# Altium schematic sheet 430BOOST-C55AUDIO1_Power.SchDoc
size A4; PageSetup: Record=PageOptions|CenterHorizontal=True|CenterVertical=True|PrintScale=1.00|XCorrection=1.00|YCorrection=1.00|PrintKind=0|BorderSize=5000000|LeftOffset=0|BottomOffset=0|Orientation=2|PaperLength=1000|PaperWidth=1000|Scale=100|PaperSource=7|PrintQuality=-4|MediaType=1|DitherType=10|PaperKind=A4|PrintScaleMode=1
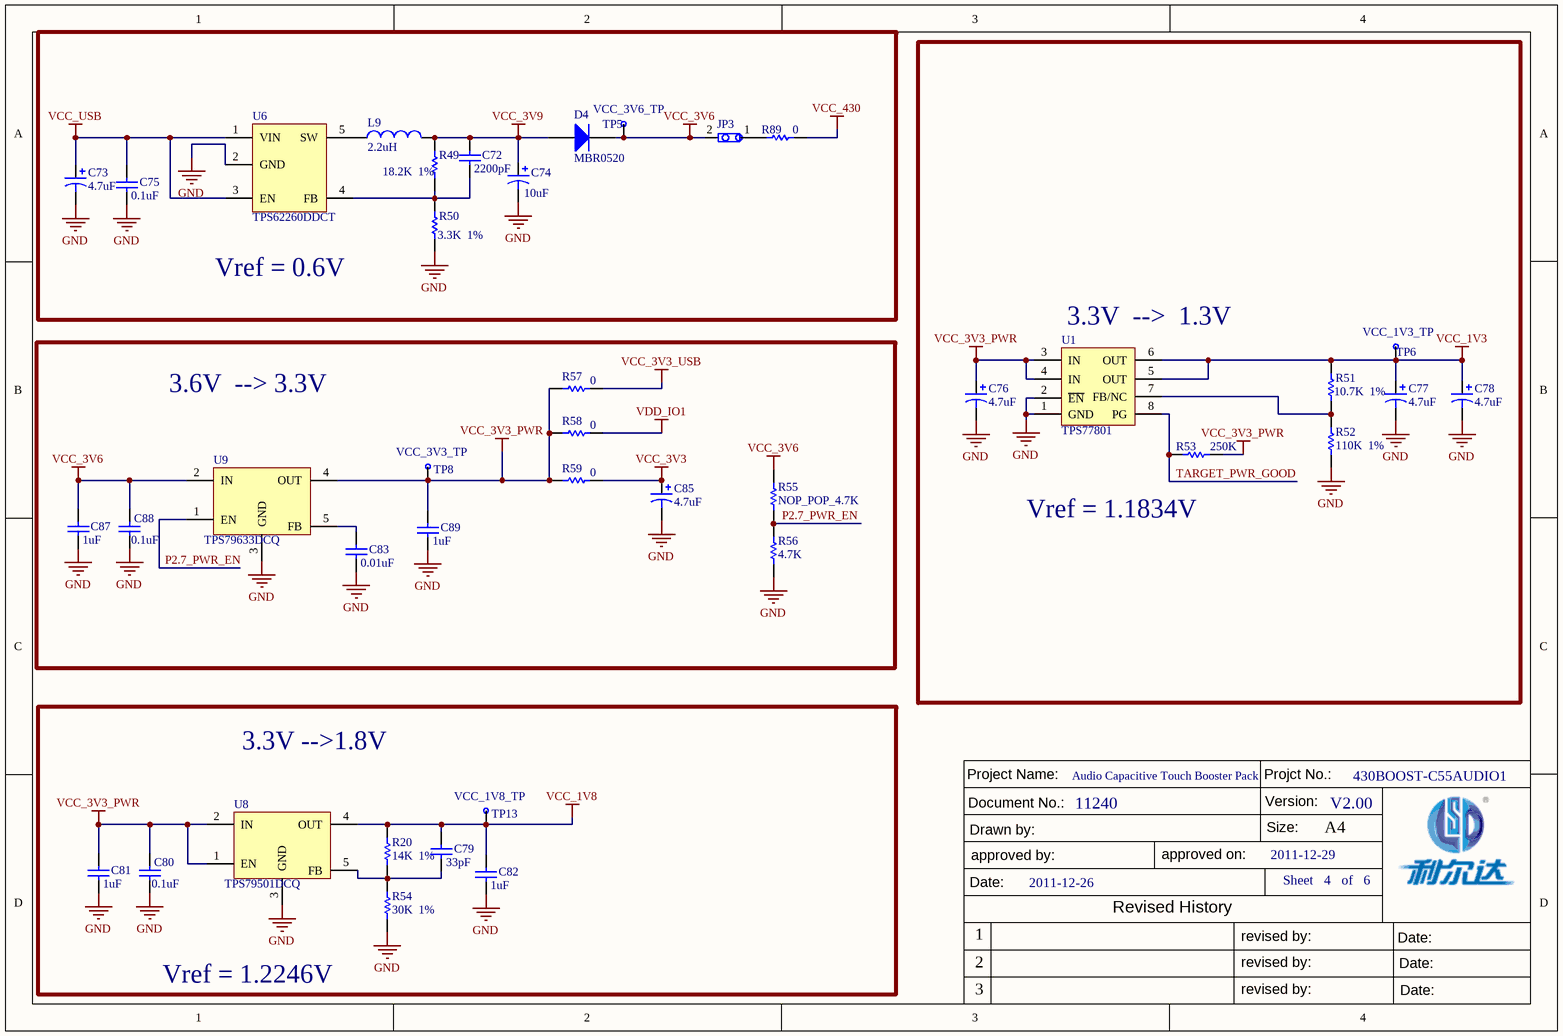
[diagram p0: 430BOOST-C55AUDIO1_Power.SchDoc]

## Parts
C72  2200pF  [0402-C]
C73  4.7uF  [0805-c]
C74  10uF  [0805-c]
C75  0.1uF  [0402-C]
C76  4.7uF  [0805-c]
C77  4.7uF  [0805-c]
C78  4.7uF  [0805-c]
C79  33pF  [0402-C]
C80  0.1uF  [0402-C]
C81  1uF  [0603-C]
C82  1uF  [0603-C]
C83  0.01uF  [0402-C]
C85  4.7uF  [0805-c]
C87  1uF  [0603-C]
C88  0.1uF  [0402-C]
C89  1uF  [0603-C]
D4  MBR0520  [SOD-123-1]
JP3  JUMPER  [SIP2-2.54]  (value not drawn)
L9  2.2uH  [VLF3010A]
R20  14K  1%  [0402-R]
R49  18.2K  1%  [0402-R]
R50  3.3K  1%  [0402-R]
R51  10.7K  1%  [0402-R]
R52  110K  1%  [0402-R]
R53  250K  [0402-R]
R54  30K  1%  [0402-R]
R55  NOP_POP_4.7K  [0402-R]
R56  4.7K  [0402-R]
R57  0  [0402-R]
R58  0  [0402-R]
R59  0  [0402-R]
R89  0  [0402-R]
TP5  VCC_3V6_TP  [SIP1-TEST]
TP6  VCC_1V3_TP  [SIP1-TEST]
TP8  VCC_3V3_TP  [SIP1-TEST]
TP13  VCC_1V8_TP  [SIP1-TEST]
U1  TPS77801  [SOIC-8P]
U6  TPS62260DDCT  [SOT-23-5P]
U8  TPS79501DCQ  [SOT-223-6]
U9  TPS79633DCQ  [SOT-223-6]

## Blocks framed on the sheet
Vref = 0.6V: C72-C75 D4 JP3 L9 R49 R50 R89 TP5 U6
3.6V  --> 3.3V: C83 C85 C87-C89 R55-R59 TP8 U9

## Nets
GND: C73.2 C74.2 C75.1 C76.2 C77.2 C78.2 C80.1 C81.1 C82.1 C83.1 C85.2 C87.1 C88.1 C89.1 R50.1 R52.1 R54.2 R56.1 U1.1(GND) U1.2(~{EN}) U6.2(GND) U8.3(GND) U9.3(GND)
VCC_1V3: C77.1 C78.1 R51.2 TP6.1 U1.5(OUT) U1.6(OUT)
VCC_1V8: C79.2 C82.2 R20.2 TP13.1 U8.4(OUT)
VCC_3V3: C85.1 R59.2
VCC_3V3_PWR: C76.1 C80.2 C81.2 C89.2 R53.2 R57.1 R58.1 R59.1 TP8.1 U1.3(IN) U1.4(IN) U8.1(EN) U8.2(IN) U9.4(OUT)
VCC_3V3_USB: R57.2
VCC_3V6: C87.2 C88.2 D4.2(K) JP3.2 R55.2 TP5.1 U9.2(IN)
VCC_3V9: C72.2 C74.1 D4.1(A) L9.2 R49.2
VCC_430: R89.2
VCC_USB: C73.1 C75.2 U6.1(VIN) U6.3(EN)
VDD_IO1: R58.2
P2.7_PWR_EN: R55.1 R56.2 U9.1(EN)
TARGET_PWR_GOOD: R53.1 U1.8(PG)
NetC72_1: C72.1 R49.1 R50.2 U6.4(FB)
NetC79_1: C79.1 R20.1 R54.1 U8.5(FB)
NetC83_2: C83.2 U9.5(FB)
NetJP3_1: JP3.1 R89.1
NetL9_1: L9.1 U6.5(SW)
NetR51_1: R51.1 R52.2 U1.7(FB/NC)

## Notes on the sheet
- (near U1) 3.3V  -->  1.3V
- (near R53) Vref = 1.1834V
- 3.3V -->1.8V
- Audio Capacitive Touch Booster Pack
- 430BOOST-C55AUDIO1
- 11240
- V2.00
- 2011-12-26
- 2011-12-29
- Sheet   4   of   6
- Vref = 1.2246V

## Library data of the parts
C72 C75 C79-C83 C87-C89 = Cap: Capacitor; Value: 100pF
C73 C74 C76-C78 C85 = Cap Pol1: Polarized Capacitor (Radial); Value: 100pF
D4 = Diode: Default Diode
L9 = Inductor: Code_IEC: 1005; Value: 10mH
R20 R49-R59 R89 = Res1: Resistor; Value: 1K
TP5 TP6 TP8 TP13 = TextPoint
U8 U9 = TPS79533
